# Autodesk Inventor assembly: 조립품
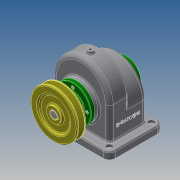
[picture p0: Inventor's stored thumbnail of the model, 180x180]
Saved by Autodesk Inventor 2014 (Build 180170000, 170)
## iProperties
Created: 2017-11
Part Number: 조립품
Document SubType Name: Assembly
Designer: sda
Author: sda
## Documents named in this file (14)
- C:\Users\sda\Desktop\471107V1032\조립품.iam
- C:\Users\sda\Desktop\471107V1032\본체.ipt
- C:\Users\sda\Desktop\471107V1032\V-벨트풀리.ipt
- C:\Users\sda\Desktop\471107V1032\뒤커버.ipt
- C:\Users\sda\Desktop\471107V1032\멈춤나사 - M4 x 10.ipt
- 멈춤나사 - M4 x 10.ipt
- C:\Users\sda\Desktop\471107V1032\베어링 6002.ipt
- C:\Users\sda\Desktop\471107V1032\볼트 M3 x 8.ipt
- C:\Users\sda\Desktop\471107V1032\스퍼기어.ipt
- C:\Users\sda\Desktop\471107V1032\앞커버.ipt
- C:\Users\sda\Desktop\471107V1032\오일 실 15 30 7.ipt
- C:\Users\sda\Desktop\471107V1032\축.ipt
- C:\Users\sda\Desktop\471107V1032\키 - 5 x 5 x 18.ipt
- C:\Users\sda\Desktop\471107V1032\키 - 6 x 6 x 22.ipt
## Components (1 placed, 1 different names)
1. V-벨트풀리:1
